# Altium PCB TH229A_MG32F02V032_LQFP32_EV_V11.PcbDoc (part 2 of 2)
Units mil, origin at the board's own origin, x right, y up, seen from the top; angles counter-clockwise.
Board outline 4094.49 x 2637.8 mil, 2 copper layers (Top Layer, Bottom Layer); 124 components, 101 nets, 554 pads, 263 vias.
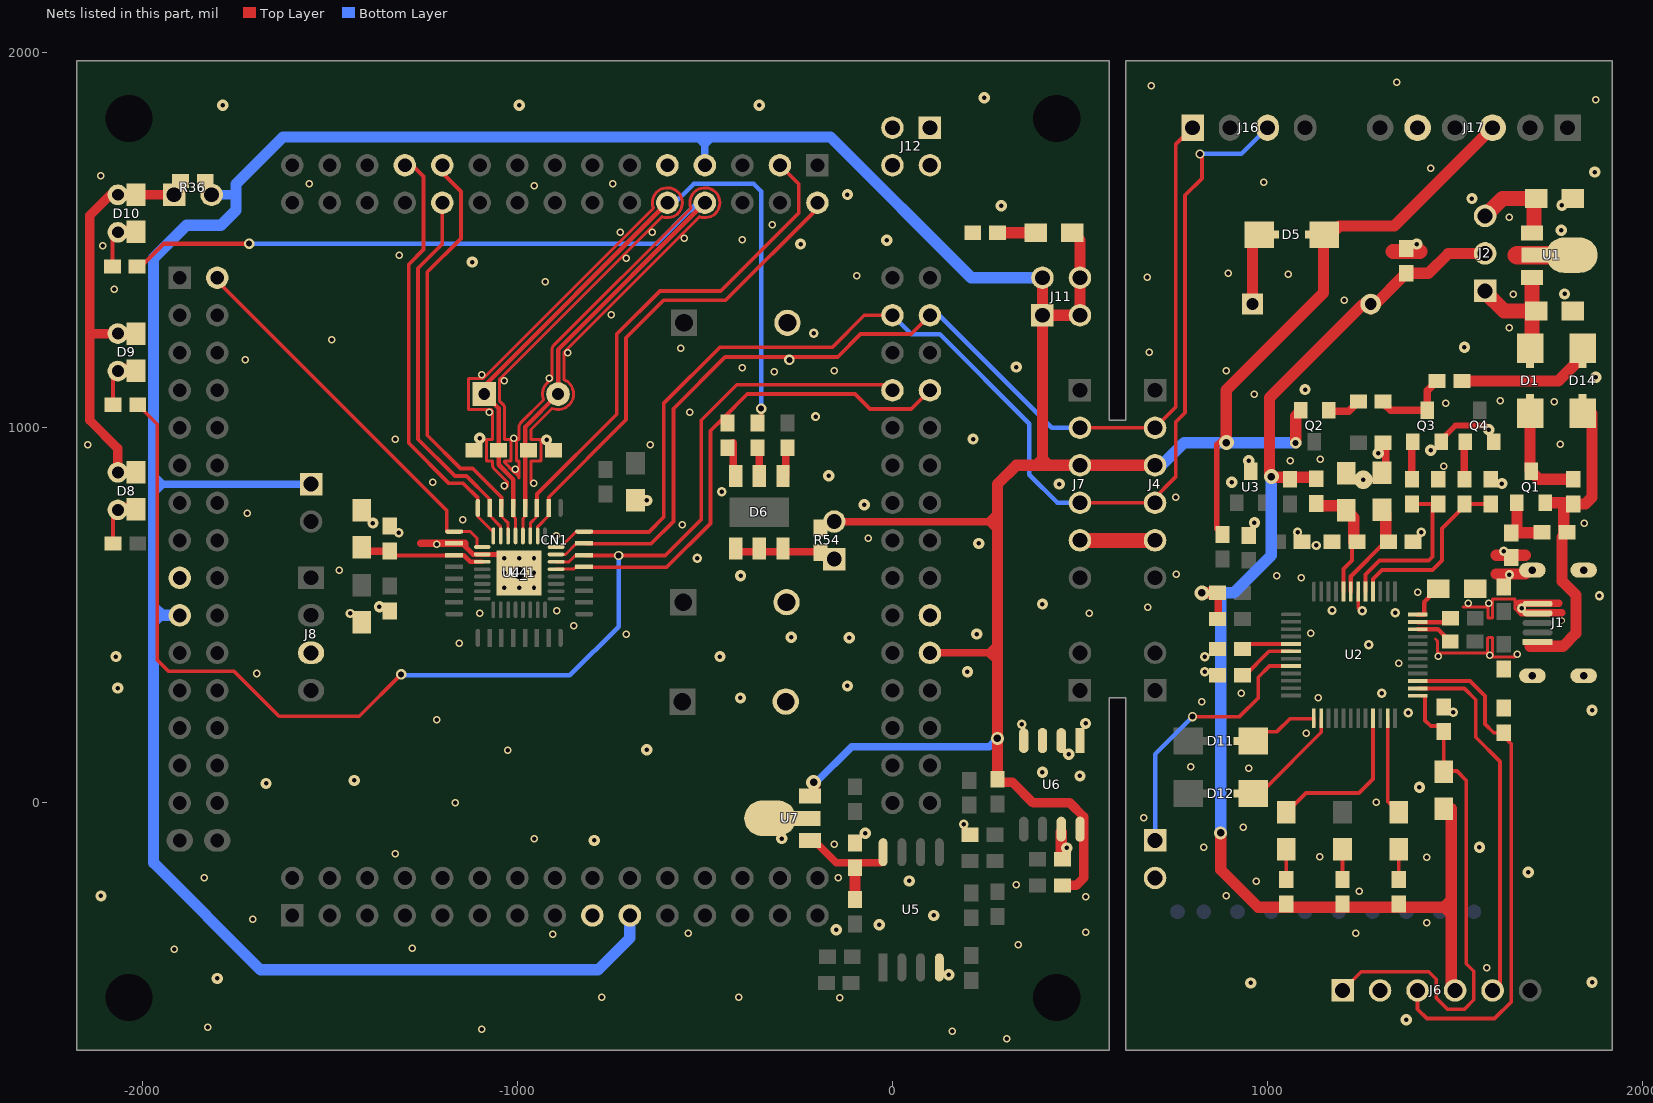
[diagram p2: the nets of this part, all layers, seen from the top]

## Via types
v1: diameter 20, hole 12, Top Layer to Bottom Layer, tented both sides, 128 vias
v2: diameter 30, hole 12, Top Layer to Bottom Layer, tented both sides, 72 vias
v3: diameter 25, hole 12, Top Layer to Bottom Layer, tented both sides, 24 vias
v4: diameter 25, hole 16, Top Layer to Bottom Layer, tented both sides, 20 vias
v5: diameter 28, hole 16, Top Layer to Bottom Layer, 7 vias
v6: diameter 40, hole 20, Top Layer to Bottom Layer, tented both sides, 5 vias
v7: diameter 30, hole 16, Top Layer to Bottom Layer, tented both sides, 3 vias
v8: diameter 35, hole 20, Top Layer to Bottom Layer, tented both sides, 2 vias
v9: diameter 15, hole 12, Top Layer to Bottom Layer, tented both sides, 1 vias
v10: diameter 50, hole 12, Top Layer to Bottom Layer, tented both sides, 1 vias

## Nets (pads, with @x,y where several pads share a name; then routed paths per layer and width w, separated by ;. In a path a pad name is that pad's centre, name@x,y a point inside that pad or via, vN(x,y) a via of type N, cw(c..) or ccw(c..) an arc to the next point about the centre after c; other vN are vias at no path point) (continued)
MG_PC0: CN1.53 R28.1 U4.13 U4_1.13 | length 1423.4
  Top Layer w8: U4_1.13@-896.61,623.17 -850.2,623.17 -844.29,629.07 U4.13@-821.81,629.07
  Top Layer w10: U4.13@-817.87,628.01 -601.99,628.01 -485,745 -485,991.93 -451.96,1024.96 -386.93,1090 -305,1090 ; -250,1090 -305,1090 ; CN1.53@100,1100 50,1050 -60,1050 -100,1090 -305,1090
MG_PC1: CN1.54 R34.1 U4.14 U4_1.14 | length 3548.1
  Top Layer w8: U4_1.14@-896.61,642.85 -862.51,642.85 -844.8,660.57 U4.14@-821.81,660.57
  Top Layer w10: R34.1@-2012.04,1061.26 -1960.04,1009.26 -1960.04,381.26 -1930.04,351.26 -1755.04,351.26 -1635.04,231.26 -1421.47,231.26 v5(-1310.04,342.69) ; U4.14@-817.87,659.5 v4(-730,659.5) -605.5,659.5 -509.75,755.25 -509.75,1020.25 -415.25,1114.75 -265,1114.75 ; -250,1114.75 -265,1114.75 ; CN1.54@0,1100 -14.75,1114.75 -265,1114.75
  Bottom Layer w12: v5@-1310.04,340 -860,340 -730,470 v4(-730,659.5)
MG_PC8: CN1.62 U4.18 U4_1.18 | length 1291
  Top Layer w8: U4_1.18@-945.83,711.75 -945.83,736.54 -916.3,766.06 U4.18@-916.3,786.55
  Top Layer w10: U4.18@-916.3,789.43 -916.3,815 -710,1021.3 -710,1240 -610,1340 -445,1340 -200,1585 CN1.62@-200,1600
MG_PC9: CN1.63 U4.19 U4_1.19 | length 1434.5
  Top Layer w8: U4_1.19@-965.51,711.75 -965.51,745.85 -947.8,763.57 U4.19@-947.8,786.55 -947.8,823.5
  Top Layer w10: U4.19@-947.8,789.43 -947.8,823.5 -735,1036.3 -735,1250 -620,1365 -457.63,1365 -250,1572.63 -250,1650 CN1.63@-300,1700
MG_PD0: CN1.81 U4.22 U4_1.22 | length 1151.7
  Top Layer w8: U4.22@-1042.28,786.55 -1042.28,763.57 -1024.57,745.85 U4_1.22@-1024.57,711.75
  Top Layer w10: CN1.81@-1200,1680 -1190,1670 ; CN1.81@-1190,1690 -1190,1670 ; U4.22@-1042.28,789.43 -1042.28,814.83 -1118.71,891.26 -1151.26,891.26 -1240,980 -1240,1415 -1150,1505 -1150,1630 -1190,1670
MG_PD1: CN1.82 U4.23 U4_1.23 | length 1001.5
  Top Layer w8: U4.23@-1073.78,786.55 -1073.78,766.06 -1044.25,736.54 U4_1.23@-1044.25,711.75
  Top Layer w10: CN1.82@-1200,1600 -1200,1490 -1264.75,1425.25 -1264.75,969.75 -1166.57,871.57 -1135.9,871.57 U4.23@-1073.78,809.46
MG_PD2: CN1.83 U4.24 U4_1.24 | length 1160.9
  Top Layer w8: -1105.28,813.11 U4.24@-1105.28,786.55 -1105.28,763.5 -1063.94,722.16 U4_1.24@-1063.94,711.75
  Top Layer w10: CN1.83@-1300,1720 -1290,1710 -1250,1670 -1250,1475 -1289.5,1435.5 -1289.5,959.5 -1181.89,851.89 -1144.05,851.89 -1105.28,813.11
MG_PD7: CN1.92 U4.25 U4_1.25 | length 1035.9
  Top Layer w8: U4.25@-1168.27,723.56 -1125.28,723.56 -1107.94,706.22 -1107.94,682.22 U4_1.25@-1093.47,682.22
  Top Layer w10: CN1.92@-1800,1400 -1800,1391.22 -1188.04,779.26 U4.25@-1188.04,723.56
MG_VR0: C15.1 C17.1 U4.27 U4_1.27 | length 370.3
  Top Layer w8: -1205.04,660.57 U4.27@-1168.27,660.57
  Top Layer w10: C17.1@-1340,680 -1336.02,676.02 -1336.02,672 -1336.02,667.24 -1328.28,659.5 U4.27@-1172.2,659.5
  Top Layer w12: U4.27@-1168.27,660.57 -1143.28,660.57 -1125.57,642.85 U4_1.27@-1093.47,642.85
  Top Layer w20: C15.1@-1410.04,670.79 C17.1@-1340.04,670.79
NetC2_2: C2.2 Q1.1 R5.2 | length 170
  Top Layer w30: R5.2@1650,720 R5.2@1665,720 ; Q1.1@1665,805 Q1.1@1665,800 R5.2@1665,720 ; C2.2@1735,720 1731.96,720 R5.2@1665,720
NetC6_1: C6.1 C7.2 R10.2 U2.44 | length 306.5
  Top Layer w11: U2.44@1202.19,563.13 1202.19,623.49 1224.96,646.26 C7.2@1224.96,691.26
  Top Layer w30: R10.2@1145,792 1209.96,792 C6.1@1209.96,780.79 1229.96,760.79 C7.2@1229.96,696.26
NetC8_2: C8.2 C9.1 U2.43 | length 261.6
  Top Layer w11: U2.43@1221.88,563.13 1221.88,604.18 C8.2@1314.96,697.26
  Top Layer w30: C9.1@1304.96,782.05 1314.96,772.05 C8.2@1314.96,697.26
NetC11_1: C11.1 U2.36 | length 103.2
  Top Layer w12: U2.36@1400.46,502.16 1417.16,502.16 1417.16,534.68 1454.38,571.9 C11.1@1455.75,571.9
NetD1_1: D1.1 Q1.3 R1.2 | length 306
  Top Layer w30: D1.1@1699.96,1038.39 1699.96,886.98 1723.94,863 ; Q1.3@1703,883.94 1723.94,863 ; R1.2@1815,863 1723.94,863
NetD2_1: D2.1 R6.2 | length 97
  Top Layer w10: R6.2@1050,-212 R6.2@1050,-203.74 D2.1@1050,-122.95 D2.1@1050,-115
NetD3_1: D3.1 R9.2 | length 97
  Top Layer w10: R9.2@1350,-212 R9.2@1350,-203.74 D3.1@1350,-122.95 D3.1@1350,-115
NetD4_1: D4.1 R11.2 | length 97
  Top Layer w10: R11.2@1200,-212 R11.2@1200,-203.74 D4.1@1200,-122.95 D4.1@1200,-115
NetD5_1: D5.1 SW1.1 | length 215.1
  Top Layer w20: D5.1@960.83,1515 D5.1@978.35,1515 D5.1@1011.81,1515
  Top Layer w30: SW1.1@960.04,1330 D5.1@960.04,1494.13
NetD6_1: D6.1 D6.3 D6.5 R54.1 | length 270
  Top Layer w20: D6.3@-355,670 -415.04,670 -292.01,670 R54.1@-205.04,670
NetD6_2: D6.2 R28.2 | length 88.5
  Top Layer w20: D6.2@-425,871.46 -425,947 R28.2@-425,960
NetD6_4: D6.4 R29.2 | length 75.5
  Top Layer w20: D6.4@-355,871.46 R29.2@-355,947
NetD6_6: D6.6 R30.2 | length 83.5
  Top Layer w20: D6.6@-285,871.46 -285,947 R30.2@-285,955
NetD7_2: D7.2 R31.2 | length 101.6
  Top Layer w30: R31.2@280,1520 D7.2@381.58,1520
NetD8_1: D8.1 D9.1 D10.1 R36.1 | length 1087.6
  Top Layer w25: -2140.13,1020.13 -2140.04,1020.04 ; D9.1@-2065.04,1251.26 -2140.04,1251.26 ; D8.1@-2016.36,881.13 -2065.04,881.13 D8.1@-2065.04,881.26 -2065.04,945.04 -2140.04,1020.04 ; R36.1@-1915.04,1621.26 -2016.36,1621.26 D10.1@-2065.04,1621.26 -2084.72,1621.26 -2140.04,1565.94 -2140.04,1251.26 ; -2140.04,1020.04 -2140.04,1251.26
NetD8_2: D8.2 R33.2 | length 198.8
  Top Layer w10: R33.2@-2078.04,691.26 -2078.04,768.26 D8.2@-2065.04,781.26 -2063.59,782.71 -2050.04,796.26 -2016.36,796.26 D8.2@-2015.04,796.26
  Top Layer w30: D8.2@-2063.59,782.71 D8.2@-2016.36,782.71
NetD9_2: D9.2 R34.2 | length 153.6
  Top Layer w10: R34.2@-2078.04,1061.26 -2078.04,1138.26 D9.2@-2065.04,1151.26 ; D9.2@-2063.59,1152.71 D9.2@-2065.04,1151.26 ; D9.2@-2015.04,1166.26 -2016.36,1166.26 -2050.04,1166.26 D9.2@-2065.04,1151.26
NetD10_2: D10.2 R35.2 | length 151.6
  Top Layer w10: R35.2@-2079.48,1429.81 -2079.48,1506.81 D10.2@-2065.04,1521.26 -2051.48,1534.81 D10.2@-2016.48,1534.81
NetD11_1: D11.1 U2.13 | length 209.6
  Top Layer w10: D11.1@946.61,150 D11.1@961.61,165 D11.1@976.61,180 ; D11.1@985,190 1025,190 1059.06,224.06 U2.13@1120.92,224.06 ; U2.13@1123.45,208.45 U2.13@1123.45,225.65
NetD12_2: D12.2 U2.14 | length 287
  Top Layer w10: D12.2@955,40 961.61,40 995,40 1143.14,188.14 U2.14@1143.14,225.65
NetD14_2: D14.2 R17.1 | length 348.7
  Top Layer w30: R17.1@1517.96,1125 1769.96,1125 ; 1774.96,1125 D14.2@1834.04,1184.07 ; D14.2@1823.11,1208.15 D14.2@1834.96,1208.15 ; D14.2@1829.04,1184.07 D14.2@1829.96,1185
NetQ2_1: Q2.1 R18.2 | length 89.8
  Top Layer w20: Q2.1@1162.96,1043.94 1215.94,1043.94 R18.2@1242,1070
NetQ3_1: Q3.1 R19.2 | length 117.1
  Top Layer w20: R19.2@1385,880.04 R19.2@1385,863 Q3.1@1385,960.53 ; Q3.1@1387.5,960.53 Q3.1@1387.5,963.03
NetQ3_2: Q3.2 R17.2 R18.1 | length 192.7
  Top Layer w20: R18.1@1313,1070 1313,1061.96 1327.99,1046.97 Q3.2@1425.5,1046.97 ; 1425.5,1070 1425.5,1098.54 R17.2@1451.96,1125
NetQ4_1: Q4.1 R23.2 | length 100
  Top Layer w20: R23.2@1525,863 Q4.1@1525,960.53 ; Q4.1@1527.5,960.53 Q4.1@1527.5,963.03
NetR15_1: R15.1 U2.35 | length 108.8
  Top Layer w12: U2.35@1400.46,481.47 1430,481.47 ; 1462.26,481.47 1430,481.47 ; R15.1@1477,481.47 1430,481.47
NetR16_1: R16.1 U2.34 | length 100.1
  Top Layer w12: U2.34@1400.46,462.79 1454.21,462.79 R16.1@1487,430
ONBOARD_ICP/SWD_SCL: CN1.57 J4.2 J7.2 J16.1 U4.15 U4_1.15 | length 3027.4
  Top Layer w8: U4_1.15@-896.61,662.54 -871.83,662.54 -842.3,692.06 U4.15@-821.81,692.06
  Top Layer w10: U4.15@-817.87,691 -643.52,691 -583.99,750.53 -583.99,1051.01 -446.01,1188.99 -275.04,1188.99 -260,1188.99 ; -250,1188.99 -260,1188.99 ; CN1.57@100,1300 50,1250 -85,1250 -146.01,1188.99 -260,1188.99 ; J7.2@500,1000 J4.2@700,1000 ; J4.2@700,994 703,997 J4.2@706,1000 ; J4.2@710,1000 J4.2@706,1000 ; J16.1@800,1800 755,1755 755,1055 J4.2@700,1000 ; J4.2@700,1000 J4.2@706,1000
  Bottom Layer w12: CN1.57@100,1300 125,1300 425,1000 J7.2@500,1000
  other v5: -275.04,1181.26
ONBOARD_ICP/SWD_SDA: CN1.58 J4.4 J7.4 J16.3 U4.16 U4_1.16 | length 3536.6
  Top Layer w8: U4_1.16@-896.61,682.22 -884.08,682.22 -842.74,723.56 U4.16@-821.81,723.56
  Top Layer w10: U4.16@-817.87,722.5 -648.8,722.5 -610,761.3 -610,1065 -460,1215 -160,1215 -75,1300 CN1.58@0,1300 ; J7.4@500,800 J4.4@685,800 ; J4.4@692.5,806.5 693,807 755,869 755,1015 780,1040 780,1620 825,1665 v4@825,1730 ; J4.4@692.5,812.5 692.5,807.5 J4.4@685,800 ; J4.4@700,800 J4.4@685,800
  Bottom Layer w12: CN1.58@20,1300 CN1.58@0,1300 50,1250 125.96,1250 365,1010.96 365,875 440,800 J7.4@500,800 ; v4(820,1730) 930,1730 J16.3@1000,1800
P44: J6.5 U2.26 | length 977.3
  Top Layer w10: U2.26@1400.46,305.31 1524.69,305.31 1555,275 1555,175 1620,110 1620,-480 J6.5@1600,-500
P45: J6.3 R25.1 U2.27 | length 1381.3
  Top Layer w10: J6.3@1400,-500 1400,-550 1425,-575 1605,-575 1650,-530 1650,156.22 R25.1@1624.96,181.26 ; U2.27@1400.46,324.99 1540.01,324.99 1580,285 1580,210 1603,187 R25.1@1630,187
PASS: D3.2 U2.23 | length 264.5
  Top Layer w10: U2.23@1320.3,225.65 1320.3,3.12 1348.98,-25.55 D3.2@1350,-26.57
RST: C12.2 J6.1 R22.2 U2.25 | length 1368.1
  Top Layer w10: J6.1@1200,-500 1250,-450 1430,-450 1450,-470 1450,-520 1480,-550 1525,-550 1550,-525 1550,-448.78 1530,-428.78 1530,59.96 1504.96,85 1485,85 1478.39,91.61 C12.2@1470,100 ; U2.25@1410,285.62 1419.38,285.62 1420,285 1420,220 1435,205 1470,205 R22.2@1470,190 C12.2@1470,100 ; C12.2@1470,90 C12.2@1470,100
RST_CTRL_51: R19.1 R20.1 U2.41 | length 455
  Top Layer w10: U2.41@1261.25,563.13 1261.25,609.12 1298.38,646.26 1429.96,646.26 1440,656.3 R20.1@1440,797 ; R19.1@1385,797 R20.1@1440,797 ; R20.1@1455,797 R20.1@1440,797
RST_CTRL_ARM: R23.1 R24.1 U2.40 | length 474.6
  Top Layer w10: U2.40@1280.93,563.13 1280.93,596.93 1305.26,621.26 1439.96,621.26 1465,646.3 1465,731.3 R23.1@1522.46,788.76 ; R23.1@1525,797 R24.1@1595,797
TOOL_OPTION0: R2.1 U2.5 | length 135.2
  Top Layer w10: R2.1@933,410 946.92,423.92 U2.5@1062.48,423.92
TOOL_OPTION1: R3.1 U2.6 | length 156.1
  Top Layer w10: R3.1@933,340 940,340 1004.23,404.23 U2.6@1062.48,404.23
USBOK: D2.2 U2.21 | length 430.2
  Top Layer w10: D2.2@1050,-26.58 1051.02,-25.55 1102.83,26.26 1243.42,26.26 1280.93,63.77 U2.21@1280.93,225.65
VCC3: C20.1 R32.2 U5.8 U7.1 | length 317.5
  Top Layer w20: U7.1@-230,-100 U7.1@-220,-100 -210,-100 -150,-160 -100,-160 -30,-160 -25,-155 U5.8@-25,-136.46
  Top Layer w30: R32.2@-100,-250 C20.1@-100,-183
VCC_USB: C2.1 D14.1 J1.1 Q1.2 R1.1 | length 843.2
  Top Layer w30: 1699.96,417.48 1719.96,417.48 1787.44,417.48 1822.44,452.48 1822.44,553.78 1784.96,591.26 1784.96,708.26 C2.1@1789.88,713.18 ; Q1.2@1740,800 1792,800 ; 1789.88,786.88 1789.88,721.26 C2.1@1789.88,713.18 ; C2.1@1797.96,721.26 C2.1@1789.88,713.18 ; R1.1@1805,797 R1.1@1815,797 1846.96,797 1864.96,815 D14.1@1864.96,1038.39
VCP_OPTION: J3.1 U2.8 | length 722
  Top Layer w10: v4(799.96,230) 925,230 975,280 975,335 1004.86,364.86 U2.8@1062.48,364.86
  Bottom Layer w12: J3.1@700,-100 700,130.04 v4(799.96,230)
VDD: C12.1 J2.2 J6.4 R4.1 R6.1 R9.1 R10.1 R11.1 R12.1 R13.1 R14.2 SW1.2 | length 3588.5
  Top Layer w11: 1458,-278 1480,-300 ; 1465,-270 1483,-252
  Top Layer w20: v6@828.07,555 R13.1@862,555 ; v6@833.07,565 R13.1@867,565 ; R12.1@869,490 R13.1@869,559.56
  Top Layer w30: v8(875,-80) 875,-178.04 974.96,-278 1050,-278 1200,-278 1350,-278 1458,-278 1483,-278 ; R14.2@1064.96,868 1059.96,868 1011.96,868 v6(1009.96,870) 1004.96,875 1004.96,1080 1253.71,1328.75 1263.79,1328.75 1268.77,1323.77 1275,1317.54 1281.23,1323.77 1369.46,1412 R4.1@1370,1412 1428.96,1412 1481.96,1465 J2.2@1580,1465 ; R14.2@1069.96,868 R10.1@1129.96,868 ; C12.1@1490,-15.21 1490,-490 J6.4@1500,-500 J6.4@1500,-490
  Bottom Layer w30: v6(825,560) 875,560 ; v8(875,-80) 875,560 ; v6(1009.96,870) 1009.96,659.96 910,560 875,560
VDD3: C5.1 J2.3 U1.1 | length 231.2
  Top Layer w40: J2.3@1580,1565 1626.26,1611.26 C5.1@1709.96,1611.26 ; U1.1@1709.96,1535 C5.1@1709.96,1611.26 ; C5.1@1715.75,1611.26 C5.1@1709.96,1611.26
VDD5: C4.1 D1.2 J2.1 U1.3 | length 318.5
  Top Layer w40: J2.1@1578.52,1363.52 1630.79,1311.26 C4.1@1704.96,1311.26 ; D1.2@1704.96,1241.61 C4.1@1704.96,1311.26 ; U1.3@1704.96,1401.26 C4.1@1704.96,1311.26 ; C4.1@1715.75,1311.26 C4.1@1704.96,1311.26
VDUT: CN1.19 CN1.39 CN1.67 CN1.109 D5.2 D7.1 J4.3 J7.3 J11.1 J11.2 J11.3 J11.4 J17.3 J18.1 Q2.2 R7.1 R36.2 R44.1 R45.1 R54.2 U6.8 U7.3 | length 12616.1
  Top Layer w11: 270,730 250,750 270,770 ; 280,370 250,400 280,430 ; 375,905 400,930 430,900
  Top Layer w15: R7.1@880,716 865,731 865,955.5 880,970.5 890,980.5 ; v6@897.75,952.75 v6@900,955
  Top Layer w20: U7.3@-230,18.11 -225,23.11 v6@-201.56,46.56 ; R54.2@-155.04,750 250,750 280,750 ; CN1.39@100,400 250,400 280,400 ; D5.2@1118.11,1515 D5.2@1151.58,1515 D5.2@1169.09,1515
  Top Layer w25: R44.1@280,55 320,55 375,0 473.11,0 510,-36.89 510,-70 510,-200 490,-220 R45.1@453,-220
  Top Layer w30: R44.1@280,73 v8(280,172) 280,370 280,400 280,430 280,750 280,850 330,900 400,900 ; J11.2@400,1400 J11.1@400,1300 ; D7.1@500,1500 J11.4@500,1400 J11.3@500,1300 J11.1@400,1300 ; J4.3@700,900 J7.3@500,900 430,900 400,900 ; v6(890,960.5) 890,980.5 890,1100.91 1149.09,1360 D5.2@1149.09,1510 ; v7@1074.96,960.5 1074.96,1030.94 Q2.2@1087.96,1043.94 ; D5.2@1164.09,1510 1169.09,1515 1191.85,1537.76 1337.76,1537.76 J17.3@1600,1800 ; 400,900 400,930 J11.1@400,1300
  Bottom Layer w20: -1970,475.04 -1945.04,500 ; -1970,530 -1940,500 ; -1970,850 -1945.04,850 ; -1970,874.96 -1945.04,850 ; -1965.08,829.96 -1945.04,850 ; J18.1@-1550,850 -1945.04,850 ; -520,1775 -500,1755 ; CN1.67@-500,1700 -500,1755 ; -500,1770 -500,1755 ; -480,1775 -500,1755 ; v6@-203.75,55 -108.75,150 258,150 v8(280,172)
  Bottom Layer w25: R36.2@-1815.04,1621.26 -1750,1621.26
  Bottom Layer w30: -1970,864.96 -1970,850 ; -1964.39,1457.42 -1881.81,1540 -1790,1540 -1750,1580 -1750,1621.26 -1750,1650 -1625,1775 -520,1775 -480,1775 -165,1775 210,1400 J11.2@400,1400 ; -1933.47,1488.34 -1970,1451.81 -1970,874.96 -1970,850 ; CN1.109@-1900,500 -1940,500 -1945.04,500 -1970,500 ; CN1.19@-700,-300 -700,-360 -785,-445 -1684.29,-445 -1970,-159.29 -1970,475.04 -1970,500 ; J4.3@718.03,900.5 778.03,960.5 v6(890,960.5) v7@1074.96,960.5 ; -1970,500 -1970,530 -1970,850
  other v6: -210,55
  other v7: 1074.96,960
VSS: C1.2 C3.2 C4.2 C5.2 C6.2 C7.1 C8.1 C9.2 C10.2 C11.2 C13.1 C14.2 C15.2 C16.2 C17.2 C18.2 C19.2 C20.2 C33.2 C34.2 CN1.17 CN1.41 CN1.69 CN1.107 J1.4 J1.5 J1.6 J1.7 J1.8 J1.9 J3.2 J4.5 J6.2 J7.5 J8.3 J12.1 J12.2 J12.3 J12.4 J17.5 Q3.3 Q4.3 R2.2 R3.2 R4.2 R5.1 R8.2 R20.2 R21.2 R22.1 R24.2 R25.2 R31.1 SW2.2 SW3.2 SW4.2 U1.2 U2.42 U3.3 U4.26 U4_1.26 U4_1.33 U5.4 U6.1 U6.2 U6.3 U6.4 U6.7 U7.2 | length 6459
  Top Layer w8: -1140,692.06 -1134,681.39 ; -1134,678.28 -1134,681.39 ; -1134,694.22 -1134,681.39 ; -1130,672.22 -1130,674.28 -1134,681.39 ; v1@-1033.79,837.45 -1030.67,840.57 -1026.79,844.45 -1026.79,845 -1026.79,855.38 -1061.3,889.89 ; -999.47,873.32 cw(c-1010.79,862.01) -995.29,865.99 ; v1@-963.29,851.9 v1@-963.29,853.12 ; v1@-956.29,846.12 -959.18,849.01 v1@-963.29,853.12 ; 1447.5,436.97 1453.5,430.97 1453.5,400 1454.96,400 1519.5,400 ; 1520.5,400 1586.5,400 1586.5,439.46 ; 1521.34,522.31 1534.96,522.31 1587.34,522.31 1587.34,493.47 1600,493.47 1600,531.9 1600,543.5 1660,543.5 1660,517.27 1667.79,509.48 1669.96,507.31 ; 1588.51,441.47 1600,441.47 1600,394 1600,389.5 1660,389.5 v1@1660,396.5 ; -1066,901.22 ccw(c-1050,901.22) -1061.3,889.89 ; -1066,901.22 ccw(c-1050,901.22) -1061.31,889.91 ; -1066,901.22 -1066,911 -1082.5,911 -1082.5,969 -1066,969 -1066,1041.5 -1066,1044.95 -1068.83,1047.78 -1069.56,1048.5 -1075.1,1048.5 -1129.92,1048.5 -1129.92,1131.5 -1095,1131.5 -1091.13,1131.5 -1087.86,1134.77 -637.24,1585.39 cw(c-600,1600) -560,1600 cw(c-600,1600) -614.61,1562.76 -647.73,1529.64 -717.73,1459.64 -1043.74,1133.64 -1046.93,1130.44 -1046.93,1125 -1046.93,1071.13 -1038.7,1062.9 ; -1038.69,1062.89 cw(c-1050,1051.58) -1034,1051.58 ; -1038.7,1062.9 cw(c-1050,1051.58) -1034,1051.58 ; -1034,1051.58 -1034,969 -1017.5,969 -1017.5,911 -1034,911 -1034,907.85 -1010.63,884.47 -999.49,873.34 cw(c-1010.79,862.01) -995.29,865.99 ; -995.29,865.99 -995.29,890 -995.29,911 -1002.5,911 -1002.5,969 -995.29,969 -995.29,1002.28 ; -995.29,1002.28 cw(c-979.29,1002.28) -990.59,1013.61 ; -995.29,1002.28 cw(c-979.29,1002.28) -990.61,1013.6 ; -990.59,1013.61 -929.96,1074.24 cw(c-891.58,1090) -907.58,1128.29 -907.58,1132.69 -907.58,1208.42 ; v1@-963.29,853.12 -963.29,911 -937.5,911 -937.5,967.56 -937.5,969 -963.29,969 -963.29,995.66 -907.33,1051.61 ccw(c-891.58,1090) -850.08,1090 ccw(c-891.58,1090) -875.58,1128.29 -875.58,1200 -875.58,1201.8 -871.24,1206.14 -563.74,1513.64 -514.61,1562.76 ccw(c-500,1600) -460,1600 ccw(c-500,1600) -537.24,1585.39 -902.87,1219.75 ; -907.58,1208.42 cw(c-891.58,1208.42) -902.89,1219.74 ; -907.58,1208.42 cw(c-891.58,1208.42) -902.87,1219.75
  Top Layer w10: v1@-1217.01,692.06 v1@-1215.1,692.06 ; 1241.56,519.01 U2.42@1241.56,563.13
  Top Layer w13: U4.26@-1147.78,692.06 -1134,678.28 -1130,674.28 -1118.25,662.54 U4_1.26@-1093.47,662.54 U4_1.33@-1040,662.54
  Top Layer w15: Q3.3@1470.25,975.29 1501.2,1006.24 1578.66,1006.24 v2(1589.9,995)
  Top Layer w20: -1257.01,692.06 -1215.1,692.06 U4.26@-1168.27,692.06 -1147.78,692.06 -1140,692.06 ; C9.2@1315,868 1315,880.47 1315,932.44 1315,960 R21.2@1315,965.53 ; 1671.04,532.9 1677.17,532.9 1719.96,532.9 1776.95,532.9 ; v3@1677.17,507.31 1719.96,507.31 1784.9,507.31
  Top Layer w30: C34.2@450,-151.9 450,-150 450,-120 U6.7@450,-78.1 ; 1610,610 1630,610 1644.9,610 J1.6@1687,610 ; 1610,660 1629.96,660 1650,660 1687,660
  Top Layer w40: J7.5@500,700 J4.5@700,700 ; 1334.9,1470 1370,1470 1397.56,1470 1406,1470
  Top Layer w50: 1664.96,1460.31 U1.2@1728.58,1460.31 U1.2@1804.96,1460.31
  Bottom Layer w11: CN1.69@-600,1700 CN1.69@-583.78,1700
  other v1: 304.9,-628.74 159.96,-608.1 -1095.1,-603.74 -1825.1,-598.74 -140.04,-520 -775.04,-518.1 -410.04,-518.1 1584.9,-440 -1915.1,-390 -1280,-388.1 334.9,-378.74 -905,-350 -545,-348.1 1234.96,-348.1 514.9,-345 1424.9,-320 -1705.1,-310 514.9,-250 889.96,-248.1 1244.9,-235 329.96,-218.1 969.96,-208.74 -1835.1,-200 -145.1,-200 1424.9,-145 1139.45,-143.74 -1325.1,-135 829.96,-118.1 -155.1,-110 -955.1,-95 934.9,-65 670,-40 -1165.1,0 1290,1.9 950,91.9 794.9,96 -1025,140 1103,186 -1215,221.9 824.9,270 1134.9,280 929.96,291.9 -1695.1,345 1350,371.9 1454.96,391.26 1592.5,394 1666,396.5 -1155.1,425 -710,450 1115,451.9 -850,471.9 -1100,505 524.9,505 -895,511.9 680,521.9 1534.96,531.84 1589.96,531.9 1400,561.9 1090,600 1024.9,605 756.96,609.26 -1475.1,620 -1215.1,690 -65.1,705 -896.61,711.75 -560,741.9 1844.9,745 -1145.1,755 -1720,771.9 754.9,815 -1035.1,845 -956.29,851.9 -1225.1,855 -1005.1,890 1469.96,896.93 1059.96,911.9 1139.96,916.26 -2145.1,955 -645.1,955 1779.96,956.26 -1325.1,970 -1010,971.9 -1075.1,1041.5 -540,1041.9 1474.9,1065 1764.9,1070 1619.96,1071.9 964.9,1090 -1035.1,1125 -914.58,1132.69 -1095,1141.9 -315.1,1150 -155,1151.9 890,1151.9 -400,1160 -1725,1181.9 -865.1,1200 684.96,1201.9 -565,1211.9 -1495.1,1235 1644.96,1266.26 -750,1301.9 1204.9,1340 1654.9,1356.26 -2075.1,1370 -925.1,1390 679.96,1401.9 -95.1,1405 1054.9,1410 895,1411.9 -710,1451.9 -1315.1,1460 -2105.1,1485 -400,1501.9 -555.1,1505 -725,1521.9 -640,1521.9 -320,1541.9 1644.96,1561.9 -955.1,1645 -1555.1,1650 -745.1,1650 990,1655 -2110,1671.9 1435,1691.9 1874.9,1875 689.96,1911.9 1344.96,1921.9
  other v2: 1370,-578.1 954.9,-480 1865,-478.1 -1800,-468.1 150,-458.1 -150,-338.1 -35.1,-325 110,-300 -2110.04,-248.1 45,-208.1 1694.9,-185 464.9,-120 1564.96,-118.1 -795.1,-100 -295.1,-95 -72.31,-80.84 1405,41.9 -1670,51.9 -1435.1,60 500,71.9 400,81.9 470,130 -655.04,141.9 515,211.9 1865,246.9 -405.1,280 -2065.04,306.26 -120,311.9 200,350 -2070,390 -460,390 -115.1,440 -270,441.9 224.9,450 -1367.66,523 400,530 -405,605.87 230,691.9 -1385,746 964.96,746.93 -75.1,795 -655.04,806.26 444.9,850 1624.96,851.26 904.9,855 -170,871.9 950,911.9 1294.96,932.44 1434.9,940 -922,967.56 214.9,970 -1100,971.9 1099.96,1101.9 1874.9,1135 330,1161.9 1524.96,1215 1792,1356.9 -1120,1441.9 -245.1,1490 1397.56,1490 -15.1,1500 1783,1526.9 290,1591.9 1784.9,1593 1544.9,1611 -120,1621.9 1872,1681.9 -1785.1,1860 -995.1,1860 -355.1,1860 244.9,1880
  other v3: 190,-57 344.9,210 1374.9,240 1494.96,241.26 1304.96,291.9 833.07,350 833.07,390 1270,421.9 -1445,505 1340,507 1252,512 1172,513 1677.17,518.86 1884.9,552.71 1644.9,608 -520,651.9 1629.96,671.26 1129.96,686.26 -1316,720 1079.96,721.26 1409.96,721.26 -455.1,830 -205.1,1030 -210.04,1251.9
  other v9: 1784.9,486.26
  other v10: 1254.96,861.26
XIN/MG_PC13: C19.1 CN1.68 R35.1 U4.20 U4_1.20 X1.2 | length 2695.3
  Top Layer w8: U4_1.20@-985.2,711.75 -985.2,758.17 -979.29,764.07 U4.20@-979.29,786.55
  Top Layer w12: R35.1@-2012.04,1421.26 -2008.48,1424.81 -1942.04,1491.26 v5(-1715.04,1491.26) ; U4.20@-979.29,786.55 -979.29,940 -979.29,1002.28 X1.2@-891.58,1090 -891.58,1208.42 CN1.68@-500,1600
  Bottom Layer w12: v5(-1715.04,1491.26) -628.74,1491.26 -540,1580 ; CN1.68@-520,1600 -540,1580 ; CN1.68@-500,1580 -540,1580
XOUT/MG_PC14: C18.1 CN1.70 R29.1 U4.21 U4_1.21 X1.1 | length 2018.3
  Top Layer w8: U4.21@-1010.79,786.55 -1010.79,764.07 -1004.88,758.17 U4_1.21@-1004.88,711.75
  Top Layer w10: R29.1@-350.04,1013 v5(-350.04,1051.26)
  Top Layer w12: U4.21@-1010.79,789.43 -1010.79,862.01 -1050,901.22 C18.1@-1050,940 -1050,1051.58 X1.1@-1088.42,1090 -1088.42,1111.58 CN1.70@-600,1600
  Bottom Layer w12: CN1.70@-590,1610 -570,1610 ; CN1.70@-580,1600 -570,1610 ; v5(-350.04,1051.26) -350,1630 -370,1650 -530,1650 -570,1610
pads on no net: CN1.1 CN1.2 CN1.7 CN1.8 CN1.9 CN1.10 CN1.15 CN1.16 CN1.18 CN1.20 CN1.21 CN1.22 CN1.23 CN1.24 CN1.25 CN1.26 CN1.27 CN1.28 CN1.29 CN1.30 CN1.31 CN1.32 CN1.37 CN1.38 CN1.40 CN1.42 CN1.43 CN1.44 CN1.45 CN1.46 CN1.47 CN1.48 CN1.49 CN1.50 CN1.51 CN1.52 CN1.55 CN1.56 CN1.60 CN1.61 CN1.64 CN1.65 CN1.66 CN1.71 CN1.72 CN1.73 CN1.74 CN1.75 CN1.76 CN1.77 CN1.78 CN1.79 CN1.80 CN1.84 CN1.85 CN1.86 CN1.87 CN1.88 CN1.89 CN1.90 CN1.91 CN1.93 CN1.94 CN1.95 CN1.96 CN1.97 CN1.98 CN1.99 CN1.100 CN1.101 CN1.102 CN1.103 CN1.104 CN1.105 CN1.106 CN1.108 CN1.110 CN1.111 CN1.112 CN1.113 CN1.118 CN1.119 CN1.120 CN1.121 CN1.122 D6.0 J6.6 J7.1 J8.2 J8.4 U2.1 U2.2 U2.3 U2.4 U2.7 U2.24 U2.28 U2.29 U2.30 U2.32 U2.37 U2.38 U2.39 U2.46 U4_1.34 U4_1.35 U4_1.36 U4_1.37 U4_1.38 U4_1.39 U4_1.40 U4_1.41 U4_1.42
copper on no net: | length 25.4
  Top Layer w10: -1900,1300 -1900,1305 ; -1800,1300 -1779.65,1300

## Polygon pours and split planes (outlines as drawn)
VSS on Bottom Layer "Top Layer-No Net" (hatched 90Degree grid 10 track 10, remove dead copper, pour order 1001): -2150.04,-638.74 1894.96,-638.74 1894.96,1935 -2150.04,1935
VSS on Top Layer "Top Layer-No Net" (hatched 90Degree grid 10 track 10, remove dead copper, pour order 1001): -2150.04,-638.74 1894.96,-638.74 1894.96,1935 -2150.04,1935

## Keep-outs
Keep-Out Layer:
  circle w7.88: c-2035.04,1824.68 r133.86
  circle w7.88: c438.35,1824.68 r133.86
  circle w7.88: c438.35,-518.74 r133.86
  circle w7.88: c-2035.04,-518.74 r133.86
  lines w15: -2175.04,-658.74 578.35,-658.74 578.35,280 621.65,280 621.65,-658.74 1919.45,-658.74 1919.45,1979.06 621.65,1979.06 621.65,1020 578.35,1020 578.35,1979.06 -2175.04,1979.06 -2175.04,-658.74

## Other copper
Top Layer:
  pour cut-out: 534.96,1965 654.96,1965 654.96,-658.74 534.96,-658.74
Bottom Layer:
  region net VSS: -916.26,543.95 -916.26,683.95 -1066.26,683.95 -1066.26,543.95
  pour cut-out: 534.96,1861.26 654.96,1861.26 654.96,-658.74 534.96,-658.74

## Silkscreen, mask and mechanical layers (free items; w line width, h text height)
Top Overlay:
  circle w10: c-2035.04,1824.68 r137.8
  circle w10: c438.35,1824.68 r137.8
  circle w4: c438.35,-518.74 r137.8
  circle w10: c-2035.04,-518.74 r137.8
  text "PD2" at -1280,1765 h50 r90
  text "PD0" at -1180,1765 h50 r90
  text "GND" at -580,1765 h50 r90
  text "VDUT" at -480,1765 h50 r90
  text "PC9" at -280,1765 h50 r90
  text "When J16 Open," at 665,1675 h45
  text "SCL" at 1720,1660 h35 r90
  text "CLK" at 1820,1660 h35 r90
  text "RST" at 1320,1650 h37 r90
  text "GND" at 1420,1645 h37 r90
  text "SDA" at 1520,1645 h37 r90
  text "VCC" at 1620,1645 h37 r90
  text "SW1 must be off." at 665,1600 h45
  text "GND" at -25.1,1580 h50
  text "Power" at 340,1580 h50
  text "VDD3" at 1389.96,1541.9 h37
  text "VDD" at 1420,1445 h37
  text "PD1" at -1180,1405 h50 r90
  text "PC8" at -180,1405 h50 r90
  text "PC6" at 165,1380 h50
  text "PD7" at -1730,1370 h50
  text "PC14" at -570,1365 h50 r90
  text "PC13" at -480,1365 h50 r90
  text "VDD5" at 1389.96,1331.9 h37
  text "PC5" at -205,1280 h50
  text "PC4" at 165,1280 h50
  text "Power On" at 1200,1185 h45
  text "VDUT" at 340,1181.9 h50
  text "Power Off" at 770,1180 h45
  text "RESET" at -615.1,1101.26 h50 r90
  text "PC1" at -190,1080 h50
  text "PC0" at 163.3,1075 h50
  text "SCL" at 355,985 h33
  text "U4 current" at -1685.1,980 h50
  text "measurement" at -1685.1,920 h50
  text "VDUT" at 320,880 h33
  text "SDA" at 350,785 h33
  text "GND" at 350,680 h33
  text "RST" at 355,580 h33
  text "GND" at -2090,570 h50
  text "VDD" at -1610,541.9 h50 r90
  text "PB11" at -610.04,481.9 h50 r90
  text "GND" at 165,480 h50
  text "VDUT" at -2130.04,471.9 h50
  text "PB8_TX" at 312,455 h38
  text "↓" at 820,400 h100 r90
  text "↓" at 430,380 h100 r90
  text "VDUT" at 165,375 h50
  text "GND" at -1610,341.9 h50 r90
  text "↓" at 380,320 h100 r270
  text "↓" at 770,300 h100 r270
  text "PA0" at -1735.1,275 h50
  text "PB9_RX" at 248,250 h38
  text "PB10" at -610.04,201.9 h50 r90
  text "PB11" at -230,180 h50
  text "PB10" at 165,180 h50
  text "PA2" at -1735,171.9 h50
  text "PA1" at -2080,170 h50
  text "TH229A_MG32F02V032" at -1490.1,160 h50
  text "PB8" at 165,105 h50
  text "PB9" at -210,90 h50
  text "LQFP32_EV_V11" at -1475.04,76.26 h45
  text "2022.02" at -900.04,71.9 h38
  text "PA3" at -2100,70 h50
  text "PA9" at -1480,-135 h50 r90
  text "PA11" at -1380,-135 h50 r90
  text "PB1" at -1075,-135 h50 r90
  text "PB3" at -980,-135 h50 r90
  text "J3 Open : Disable VCP." at 653,-360 h45
  text "J3 Short : Enable VCP." at 648,-435 h45
  text "PB0" at -1075,-490 h50 r90
  text "GND" at -770,-490 h50 r90
  text "PA8" at -1480,-495 h50 r90
  text "PB2" at -980,-495 h50 r90
  text "VDUT" at -675,-534.29 h50 r90
  text "PA10" at -1380,-535 h50 r90
Mechanical 1:
  circle w7.88: c600,350 r33
  circle w7.88: c600,640 r25
  circle w7.88: c600,758 r25
  circle w7.88: c600,845 r27
  circle w7.88: c600,955 r27
  lines w7.88: 578.35,420 621.65,420 621.65,574 578.35,574 578.35,420
  lines w8.88: -2175.04,-658.74 578.35,-658.74 578.35,280 621.65,280 621.65,-658.74 1919.45,-658.74 1919.45,1979.06 621.65,1979.06 621.65,1020 578.35,1020 578.35,1979.06 -2175.04,1979.06 -2175.04,-658.74
Mechanical 2:
  lines w6: 600,373 600,350 623,350 ; 600,663 600,640 623,640 ; 600,783 600,760 623,760 ; 600,868 600,845 623,845 ; 600,978 600,955 623,955

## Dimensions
-2175.04,-658.74 to 1919.45,-658.74 on Top Overlay
-2175.04,-658.74 to -2175.04,1979.06 on Top Overlay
